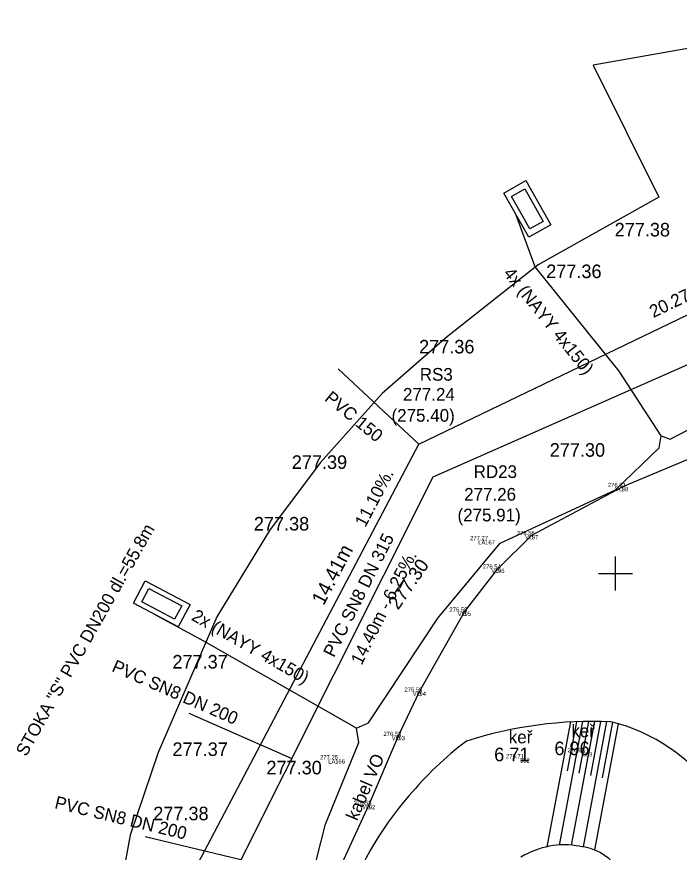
# Model space of a CAD drawing. Extents: x -601602 to -600882, y -1162594 to -1161950.
# Drawn here: x -601192.69 to -601173.11, y -1162033.24 to -1162008.56 of the extents above; entities that cross this region are included whole.
import ezdxf

# ---------------------------------------------------------------- set-up
doc = ezdxf.new("R2010")
doc.units = 0
for name, color, linetype in [('BODY', 7, 'Continuous'), ('BODY_CISLA', 7, 'Continuous'), ('BODY_KODY', 7, 'Continuous'), ('BODY_VYSKY_CELE', 7, 'Continuous'), ('G_TEXTY', 7, 'Continuous'), ('H_KOTY_VYSKOVE', 7, 'Continuous'), ('H_VYSKY_PREVZATE', 7, 'Continuous'), ('IS_EON_NN', 7, 'Continuous'), ('IS_KAN_SPLASKOVA', 7, 'Continuous'), ('IS_ODVODNENI_HDV', 7, 'Continuous'), ('IS_VO_AREAL', 7, 'Continuous'), ('KN_Hranice parcel', 7, 'Continuous'), ('X_SOUR_KRIZKY_SEVER', 7, 'Continuous')]:
    doc.layers.add(name, color=color, linetype=linetype)

# ---------------------------------------------------------------- blocks, each defined once
blk = doc.blocks.new('POINT_DISPLAY')
blk.add_line((0, 0), (0, 0))
blk = doc.blocks.new('132_9')
at = {"layer": 'IS_EON_NN'}
for points in [[(-1.5, 1.5), (1.5, 1.5), (1.5, 0), (-1.5, 0)], [(-1.1, 1.2), (1.1, 1.2), (1.1, 0.3), (-1.1, 0.3)]]:
    blk.add_lwpolyline(points, close=True, dxfattribs=at)

msp = doc.modelspace()

# ---------------------------------------------------------------- linework, layer by layer
at = {"layer": 'IS_EON_NN'}
for points in [[(-601173.65, -1162020.94), (-601174.89, -1162019.03), (-601177.37, -1162015.95), (-601177.93, -1162014.42)], [(-601173.65, -1162020.94), (-601173.38, -1162021.04), (-601163.98, -1162016.16)], [(-601182.65, -1162029.57), (-601182.3, -1162029.41), (-601180.25, -1162026.32), (-601178.41, -1162024.11), (-601175, -1162022.53), (-601173.71, -1162021.29), (-601173.65, -1162020.94)], [(-601182.65, -1162029.57), (-601187.16, -1162027), (-601188.58, -1162026.23)], [(-601184.91, -1162041.27), (-601184.79, -1162040.9), (-601184.82, -1162038.98), (-601184.4, -1162035.69), (-601183.57, -1162032.4), (-601182.58, -1162029.99), (-601182.65, -1162029.57)]]:
    msp.add_lwpolyline(points, dxfattribs=at)
at = {"layer": 'IS_KAN_SPLASKOVA'}
msp.add_line((-601183.195, -1162018.955), (-601180.812, -1162021.187), dxfattribs=at)
msp.add_lwpolyline([(-601184.326, -1162054.364), (-601187.478, -1162047.498), (-601187.521, -1162033.934), (-601180.812, -1162021.187), (-601162.543, -1162012.396)], dxfattribs=at)
at = {"layer": 'IS_ODVODNENI_HDV'}
for p, q in [((-601161.22, -1162013.7), (-601180.4, -1162022.16)), ((-601180.4, -1162022.16), (-601186.86, -1162035.03)), ((-601184.567, -1162030.461), (-601187.59, -1162029.137)), ((-601176.331, -1162029.387), (-601177.026, -1162033.072)), ((-601175.973, -1162029.373), (-601176.66, -1162033.021)), ((-601176.152, -1162029.379), (-601176.426, -1162030.833)), ((-601175.616, -1162029.369), (-601176.305, -1162033.025)), ((-601175.794, -1162029.37), (-601176.082, -1162030.9)), ((-601175.261, -1162029.376), (-601175.958, -1162033.072)), ((-601175.438, -1162029.371), (-601175.739, -1162030.968)), ((-601174.916, -1162029.439), (-601175.619, -1162033.167)), ((-601175.086, -1162029.393), (-601175.395, -1162031.035)), ((-601186.071, -1162033.458), (-601188.89, -1162032.778))]:
    msp.add_line(p, q, dxfattribs=at)
for centre, radius, start, end in [((-601175.659, -1162041.703), 12.334, 87.5867, 107.6554), ((-601176.384, -1162034.532), 5.3, 34.7611, 76.4254), ((-601173.127, -1162038.235), 10.392, 127.1322, 140.1071), ((-601174.21, -1162037.679), 9.208, 138.4369, 163.0858), ((-601176.508, -1162035.46), 2.444, 79.1985, 121.643), ((-601176.211, -1162034.631), 1.579, 354.2259, 84.1362)]:
    msp.add_arc(centre, radius, start, end, dxfattribs=at)
at = {"layer": 'IS_VO_AREAL'}
for points in [[(-601160.726, -1162019.373), (-601165.8, -1162022.93), (-601169.14, -1162021.43), (-601172.25, -1162021.38), (-601174.81, -1162022.45)], [(-601183.07, -1162033.56), (-601182.29, -1162031.84), (-601181.41, -1162029.8), (-601180.79, -1162028.49), (-601179.46, -1162026.13), (-601178.47, -1162024.86), (-601177.47, -1162023.87), (-601174.81, -1162022.45)]]:
    msp.add_lwpolyline(points, dxfattribs=at)
at = {"layer": 'KN_Hranice parcel'}
msp.add_lwpolyline([(-601158.55, -1162011.73), (-601160.13, -1162011.24), (-601167.55, -1162008.56), (-601175.66, -1162009.99), (-601173.72, -1162013.89), (-601177.28, -1162015.89), (-601179.96, -1162018), (-601181.89, -1162019.69), (-601183.72, -1162021.73), (-601185.22, -1162023.73), (-601186.78, -1162026.28), (-601188.51, -1162030.29), (-601189.34, -1162032.73), (-601190.11, -1162036.89)], dxfattribs=at)
at = {"layer": 'X_SOUR_KRIZKY_SEVER'}
for p, q in [((-601175, -1162025.5), (-601175, -1162024.5)), ((-601175.5, -1162025), (-601174.5, -1162025))]:
    msp.add_line(p, q, dxfattribs=at)

# ---------------------------------------------------------------- block references
at = {"layer": 'BODY'}
for p in [(-601174.81, -1162022.45), (-601178.85, -1162024.02), (-601177.47, -1162023.87), (-601178.47, -1162024.86), (-601179.46, -1162026.13), (-601180.79, -1162028.49), (-601181.41, -1162029.8), (-601177.82, -1162030.46), (-601175.97, -1162030.28), (-601183.28, -1162030.49), (-601182.29, -1162031.84)]:
    msp.add_blockref('POINT_DISPLAY', p, dxfattribs=at)
at = {"layer": 'IS_EON_NN'}
for p, xscale, yscale, rotation in [((-601177.93, -1162014.42), 0.49999999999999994, 0.5000000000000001, -60.67282050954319), ((-601188.58, -1162026.23), 0.5, 0.5, -27.92897870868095)]:
    msp.add_blockref('132_9', p, dxfattribs=dict(at, xscale=xscale, yscale=yscale, rotation=rotation))

# ---------------------------------------------------------------- texts
at = {"layer": 'BODY_CISLA'}
for s, p in [('98', (-601174.81, -1162022.575)), ('167', (-601178.85, -1162024.145)), ('97', (-601177.47, -1162023.995)), ('96', (-601178.47, -1162024.985)), ('95', (-601179.46, -1162026.255)), ('94', (-601180.79, -1162028.615)), ('93', (-601181.41, -1162029.925)), ('352', (-601177.82, -1162030.585)), ('353', (-601175.97, -1162030.405)), ('166', (-601183.28, -1162030.615)), ('92', (-601182.29, -1162031.965))]:
    msp.add_text(s, height=0.125, dxfattribs=at).set_placement(p)
at = {"layer": 'BODY_KODY'}
for s, p in [('VO', (-601175.009, -1162022.575)), ('LA', (-601179.054, -1162024.145)), ('VO', (-601177.669, -1162023.995)), ('VO', (-601178.669, -1162024.985)), ('VO', (-601179.659, -1162026.255)), ('VO', (-601180.989, -1162028.615)), ('VO', (-601181.609, -1162029.925)), ('LA', (-601183.484, -1162030.615)), ('VO', (-601182.489, -1162031.965))]:
    msp.add_text(s, height=0.125, dxfattribs=at).set_placement(p)
at = {"layer": 'BODY_VYSKY_CELE'}
for s, p in [('276.61 ', (-601175.222, -1162022.45)), ('276.56 ', (-601177.914, -1162023.87)), ('277.27 ', (-601179.295, -1162024.02)), ('276.54 ', (-601178.915, -1162024.86)), ('276.50 ', (-601179.905, -1162026.13)), ('276.58 ', (-601181.235, -1162028.49)), ('276.53 ', (-601181.853, -1162029.8)), ('276.96 ', (-601176.414, -1162030.28)), ('277.25 ', (-601183.725, -1162030.49)), ('276.71 ', (-601178.232, -1162030.46)), ('276.58 ', (-601182.735, -1162031.84))]:
    msp.add_text(s, height=0.125, dxfattribs=at).set_placement(p)
at = {"layer": 'G_TEXTY'}
for p in [(-601176.302, -1162029.838), (-601178.152, -1162030.018)]:
    msp.add_text('keř', height=0.375, dxfattribs=at).set_placement(p)
at = {"layer": 'H_KOTY_VYSKOVE'}
for s, p in [(' 6 96', (-601176.952, -1162030.366)), (' 6 71', (-601178.731, -1162030.546))]:
    msp.add_text(s, height=0.4, dxfattribs=at).set_placement(p)
at = {"layer": 'H_VYSKY_PREVZATE'}
for s, p in [('277.38', (-601175.023, -1162015.049)), ('277.36', (-601177.046, -1162016.279)), ('277.36', (-601180.801, -1162018.504)), ('277.30', (-601176.941, -1162021.554)), ('277.39', (-601184.563, -1162021.913)), ('277.38', (-601185.684, -1162023.733)), ('277.37', (-601188.09, -1162027.808)), ('277.37', (-601188.088, -1162030.391)), ('277.30', (-601185.312, -1162030.934)), ('277.38', (-601188.656, -1162032.289))]:
    msp.add_text(s, height=0.4, dxfattribs=at).set_placement(p)
msp.add_text('277.30', height=0.4, rotation=55.362, dxfattribs=at).set_placement((-601181.42, -1162026.098))
at = {"layer": 'IS_EON_NN'}
for s, rotation, p in [('4x (NAYY 4x150)', 308.8408, (-601178.332, -1162016.15)), ('2x (NAYY 4x150)', 330.3236, (-601187.552, -1162026.361))]:
    msp.add_text(s, height=0.375, rotation=rotation, dxfattribs=at).set_placement(p)
at = {"layer": 'IS_KAN_SPLASKOVA'}
for s, height, rotation, p in [('20.27m', 0.375, 25.6968, (-601173.882, -1162017.462)), ('PVC 150', 0.375, 320.6489, (-601183.618, -1162019.874)), ('11.10%.', 0.375, 62.2413, (-601182.391, -1162023.662)), ('STOKA "S" PVC DN200 dl.=55.8m', 0.375, 60.5749, (-601192.411, -1162030.429)), ('14.41m', 0.425, 62.2413, (-601183.622, -1162025.968))]:
    msp.add_text(s, height=height, rotation=rotation, dxfattribs=at).set_placement(p)
for s, p in [('RS3', (-601180.78, -1162019.309)), ('277.24', (-601181.278, -1162019.899)), ('(275.40)', (-601181.615, -1162020.52))]:
    msp.add_text(s, height=0.375, dxfattribs=at).set_placement(p)
at = {"layer": 'IS_ODVODNENI_HDV'}
for s, p in [('RD23', (-601179.19, -1162022.182)), ('277.26', (-601179.47, -1162022.852)), ('(275.91)', (-601179.666, -1162023.463))]:
    msp.add_text(s, height=0.375, dxfattribs=at).set_placement(p)
for s, rotation, p in [('PVC SN8 DN 315', 63.346, (-601183.316, -1162027.503)), ('14.40m - 6.25%.', 63.346, (-601182.503, -1162027.732)), ('PVC SN8 DN 200', 336.3478, (-601189.908, -1162027.879)), ('PVC SN8 DN 200', 346.4382, (-601191.592, -1162031.93))]:
    msp.add_text(s, height=0.375, rotation=rotation, dxfattribs=at).set_placement(p)
at = {"layer": 'IS_VO_AREAL'}
msp.add_text('kabel VO', height=0.375, rotation=66.666, dxfattribs=at).set_placement((-601182.635, -1162032.325))

doc.saveas('drawing.dxf')
